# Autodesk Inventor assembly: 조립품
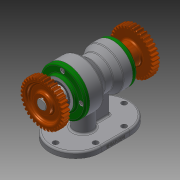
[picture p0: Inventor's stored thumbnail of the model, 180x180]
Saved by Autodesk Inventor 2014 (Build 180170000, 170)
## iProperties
Created: 2020-01
Part Number: 조립품
Document SubType Name: Assembly
Designer: kh
Author: kh
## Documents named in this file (13)
- C:\Users\kh\Desktop\700104V1032\조립품.iam
- C:\Users\kh\Desktop\700104V1032\본체.ipt
- C:\Users\kh\Desktop\700104V1032\뒤커버.ipt
- C:\Users\kh\Desktop\700104V1032\멈춤나사 M3.ipt
- C:\Users\kh\Desktop\700104V1032\베어링 6203.ipt
- C:\Users\kh\Desktop\700104V1032\베어링 6205.ipt
- C:\Users\kh\Desktop\700104V1032\볼트 M4.ipt
- C:\Users\kh\Desktop\700104V1032\스퍼기어.ipt
- C:\Users\kh\Desktop\700104V1032\앞커버.ipt
- C:\Users\kh\Desktop\700104V1032\오일 실 17 30 8.ipt
- C:\Users\kh\Desktop\700104V1032\오일 실 25 38 8.ipt
- C:\Users\kh\Desktop\700104V1032\축.ipt
- C:\Users\kh\Desktop\700104V1032\키 5 x 5 x 18.ipt
